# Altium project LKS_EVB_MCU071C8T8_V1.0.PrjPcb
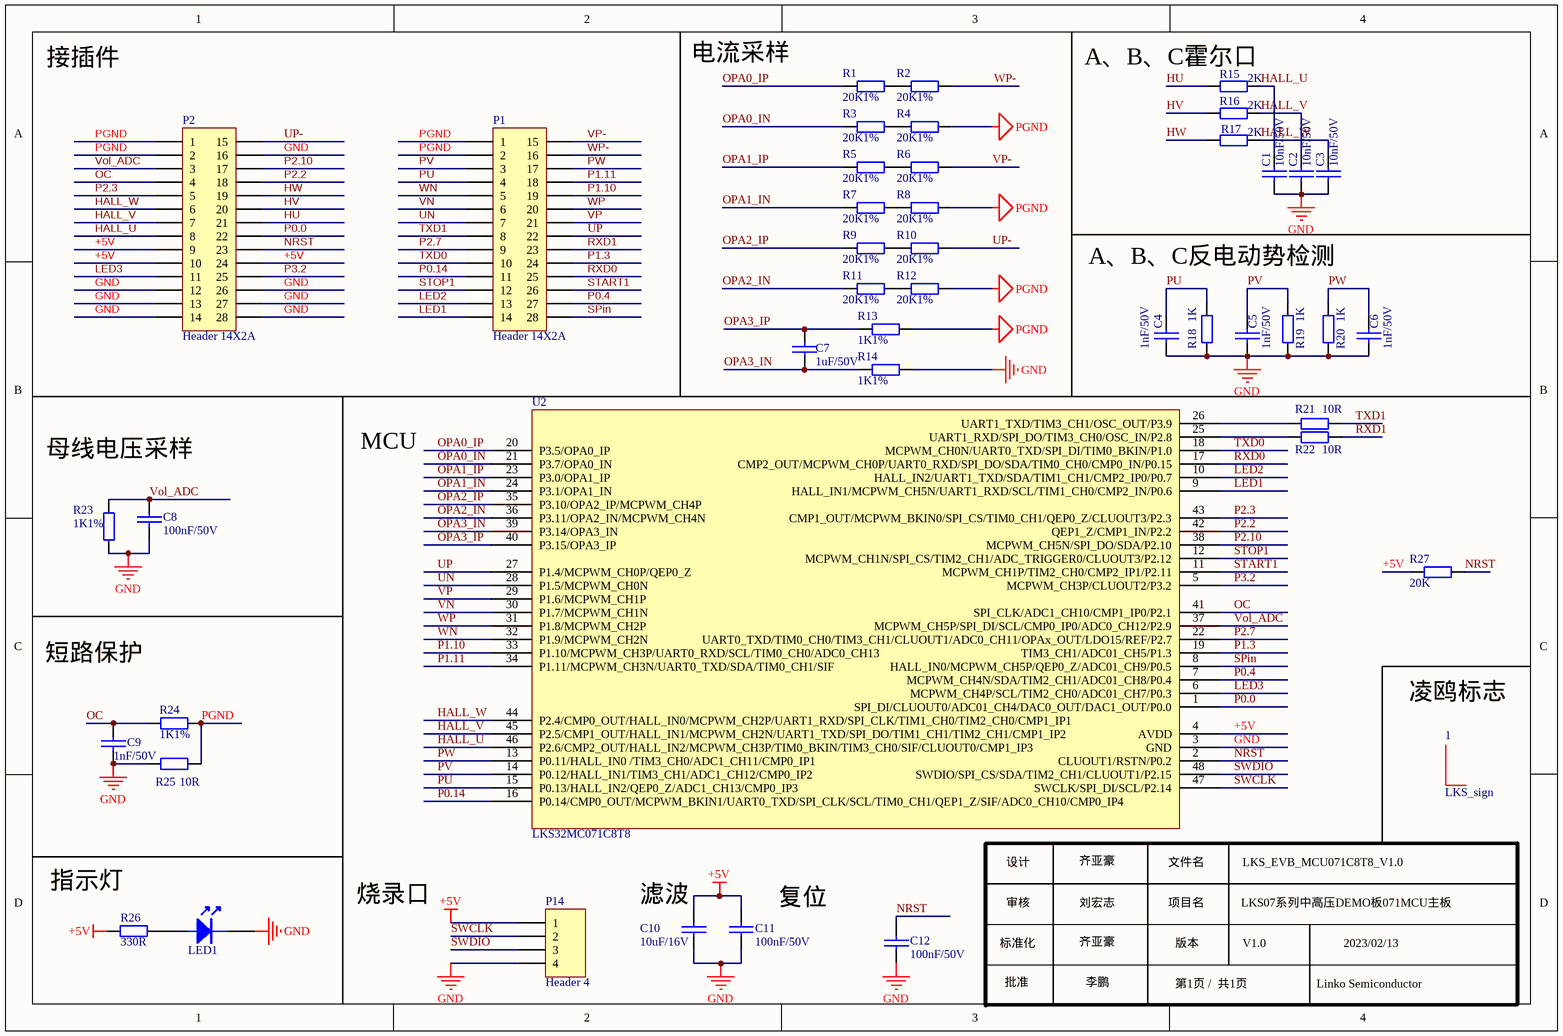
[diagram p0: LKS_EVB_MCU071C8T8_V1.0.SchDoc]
1 sheet, 45 parts. Net scope: global (net labels, ports and power ports of the same name join across sheets).
Board file: LKS_EVB_MCU071C8T8_V1.0.PcbDoc

## Sheet LKS_EVB_MCU071C8T8_V1.0.SchDoc
size A4; SheetNumber: 1; SheetTotal: 1

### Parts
1  LKS_sign  [LKS_LOGO2]
C1  10nF/50V  [0603C]
C2  10nF/50V  [0603C]
C3  10nF/50V  [0603C]
C4  1nF/50V  [0603C]
C5  1nF/50V  [0603C]
C6  1nF/50V  [0603C]
C7  1uF/50V  [0603C]
C8  100nF/50V  [0603C]
C9  1nF/50V  [0603C]
C10  10uF/16V  [0603C]
C11  100nF/50V  [0603C]
C12  100nF/50V  [0603C]
LED1  LED  [LED 0603R]  (value not drawn)
P1  Header 14X2A  [HDR2X14_CEN]
P2  Header 14X2A  [HDR2X14_CEN]
P14  Header 4  [HDR1X4]
R1  20K1%  [0603R]
R2  20K1%  [0603R]
R3  20K1%  [0603R]
R4  20K1%  [0603R]
R5  20K1%  [0603R]
R6  20K1%  [0603R]
R7  20K1%  [0603R]
R8  20K1%  [0603R]
R9  20K1%  [0603R]
R10  20K1%  [0603R]
R11  20K1%  [0603R]
R12  20K1%  [0603R]
R13  1K1%  [0603R]
R14  1K1%  [0603R]
R15  2K  [0603R]
R16  2K  [0603R]
R17  2K  [0603R]
R18  1K  [0603R]
R19  1K  [0603R]
R20  1K  [0603R]
R21  10R  [0603R]
R22  10R  [0603R]
R23  1K1%  [0603R]
R24  1K1%  [0603R]
R25  10R  [0603R]
R26  330R  [0603R]
R27  20K  [0603R]
U2  LKS32MC071C8T8  [TQFP48]

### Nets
+5V: C10.2 C11.2 P2.9 P2.10 P2.24 P14.1 R26.1 R27.2 U2.4(AVDD)
GND: C1.2 C2.2 C3.2 C4.2 C5.2 C6.2 C8.1 C9.1 C10.1 C11.1 C12.2 LED1.2(K) P2.12 P2.13 P2.14 P2.16 P2.26 P2.27 P2.28 P14.4 R14.1 R18.2 R19.2 R20.2 R23.1 R25.2 U2.3(GND)
PGND: P1.1 P1.2 P2.1 P2.2 R4.1 R8.1 R12.1 R13.1 R24.2 R25.1
HALL_U: C1.1 P2.8 R15.2 U2.46(P2.6/CMP2_OUT/HALL_IN2/MCPWM_CH3P/TIM0_BKIN/TIM3_CH0/SIF/CLUOUT0/CMP1_IP3)
HALL_V: C2.1 P2.7 R16.2 U2.45(P2.5/CMP1_OUT/HALL_IN1/MCPWM_CH2N/UART1_TXD/SPI_DO/TIM1_CH1/TIM2_CH1/CMP1_IP2)
HALL_W: C3.1 P2.6 R17.2 U2.44(P2.4/CMP0_OUT/HALL_IN0/MCPWM_CH2P/UART1_RXD/SPI_CLK/TIM1_CH0/TIM2_CH0/CMP1_IP1)
HU: P2.21 R15.1
HV: P2.20 R16.1
HW: P2.19 R17.1
LED1: P1.14 U2.9(HALL_IN1/MCPWM_CH5N/UART1_RXD/SCL/TIM1_CH0/CMP2_IN/P0.6)
LED2: P1.13 U2.10(HALL_IN2/UART1_TXD/SDA/TIM1_CH1/CMP2_IP0/P0.7)
LED3: P2.11 U2.6(MCPWM_CH4P/SCL/TIM2_CH0/ADC01_CH7/P0.3)
NRST: C12.1 P2.23 R27.1 U2.2(CLUOUT1/RSTN/P0.2)
OC: C9.2 P2.4 R24.1 U2.41(SPI_CLK/ADC1_CH10/CMP1_IP0/P2.1)
OPA0_IN: R3.2 U2.21(P3.7/OPA0_IN)
OPA0_IP: R1.2 U2.20(P3.5/OPA0_IP)
OPA1_IN: R7.2 U2.24(P3.1/OPA1_IN)
OPA1_IP: R5.2 U2.23(P3.0/OPA1_IP)
OPA2_IN: R11.2 U2.36(P3.11/OPA2_IN/MCPWM_CH4N)
OPA2_IP: R9.2 U2.35(P3.10/OPA2_IP/MCPWM_CH4P)
OPA3_IN: C7.2 R14.2 U2.39(P3.14/OPA3_IN)
OPA3_IP: C7.1 R13.2 U2.40(P3.15/OPA3_IP)
P0.0: P2.22 U2.1(SPI_DI/CLUOUT0/ADC01_CH4/DAC0_OUT/DAC1_OUT/P0.0)
P0.4: P1.27 U2.7(MCPWM_CH4N/SDA/TIM2_CH1/ADC01_CH8/P0.4)
P0.14: P1.11 U2.16(P0.14/CMP0_OUT/MCPWM_BKIN1/UART0_TXD/SPI_CLK/SCL/TIM0_CH1/QEP1_Z/SIF/ADC0_CH10/CMP0_IP4)
P1.3: P1.24 U2.19(TIM3_CH1/ADC01_CH5/P1.3)
P1.10: P1.19 U2.33(P1.10/MCPWM_CH3P/UART0_RXD/SCL/TIM0_CH0/ADC0_CH13)
P1.11: P1.18 U2.34(P1.11/MCPWM_CH3N/UART0_TXD/SDA/TIM0_CH1/SIF)
P2.2: P2.18 U2.42(QEP1_Z/CMP1_IN/P2.2)
P2.3: P2.5 U2.43(CMP1_OUT/MCPWM_BKIN0/SPI_CS/TIM0_CH1/QEP0_Z/CLUOUT3/P2.3)
P2.7: P1.9 U2.22(UART0_TXD/TIM0_CH0/TIM3_CH1/CLUOUT1/ADC0_CH11/OPAx_OUT/LDO15/REF/P2.7)
P2.10: P2.17 U2.38(MCPWM_CH5N/SPI_DO/SDA/P2.10)
P3.2: P2.25 U2.5(MCPWM_CH3P/CLUOUT2/P3.2)
PU: C4.1 P1.4 R18.1 U2.15(P0.13/HALL_IN2/QEP0_Z/ADC1_CH13/CMP0_IP3)
PV: C5.1 P1.3 R19.1 U2.14(P0.12/HALL_IN1/TIM3_CH1/ADC1_CH12/CMP0_IP2)
PW: C6.1 P1.17 R20.1 U2.13(P0.11/HALL_IN0_/TIM3_CH0/ADC1_CH11/CMP0_IP1)
RXD0: P1.25 U2.17(CMP2_OUT/MCPWM_CH0P/UART0_RXD/SPI_DO/SDA/TIM0_CH0/CMP0_IN/P0.15)
RXD1: P1.23 R22.2
SPin: P1.28 U2.8(HALL_IN0/MCPWM_CH5P/QEP0_Z/ADC01_CH9/P0.5)
START1: P1.26 U2.11(MCPWM_CH1P/TIM2_CH0/CMP2_IP1/P2.11)
STOP1: P1.12 U2.12(MCPWM_CH1N/SPI_CS/TIM2_CH1/ADC_TRIGGER0/CLUOUT3/P2.12)
SWCLK: P14.2 U2.47(SWCLK/SPI_DI/SCL/P2.14)
SWDIO: P14.3 U2.48(SWDIO/SPI_CS/SDA/TIM2_CH1/CLUOUT1/P2.15)
TXD0: P1.10 U2.18(MCPWM_CH0N/UART0_TXD/SPI_DI/TIM0_BKIN/P1.0)
TXD1: P1.8 R21.1
UN: P1.7 U2.28(P1.5/MCPWM_CH0N)
UP: P1.22 U2.27(P1.4/MCPWM_CH0P/QEP0_Z)
UP-: P2.15 R10.1
VN: P1.6 U2.30(P1.7/MCPWM_CH1N)
Vol_ADC: C8.2 P2.3 R23.2 U2.37(MCPWM_CH5P/SPI_DI/SCL/CMP0_IP0/ADC0_CH12/P2.9)
VP: P1.21 U2.29(P1.6/MCPWM_CH1P)
VP-: P1.15 R6.1
WN: P1.5 U2.32(P1.9/MCPWM_CH2N)
WP: P1.20 U2.31(P1.8/MCPWM_CH2P)
WP-: P1.16 R2.1
NetLED1_1: LED1.1(A) R26.2
NetR1_1: R1.1 R2.2
NetR3_1: R3.1 R4.2
NetR5_1: R5.1 R6.2
NetR7_1: R7.1 R8.2
NetR9_1: R9.1 R10.2
NetR11_1: R11.1 R12.2
NetR21_2: R21.2 U2.26(UART1_TXD/TIM3_CH1/OSC_OUT/P3.9)
NetR22_1: R22.1 U2.25(UART1_RXD/SPI_DO/TIM3_CH0/OSC_IN/P2.8)

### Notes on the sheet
- 接插件
- 电流采样
- A、B、C霍尔口
- A、B、C反电动势检测
- MCU
- 母线电压采样
- 短路保护
- (near 1) 凌鸥标志
- (near R26) 指示灯
- 烧录口
- (near C10) 滤波
- (near C11) 复位
- 设计
- 审核
- 齐亚豪
- 刘宏志
- 文件名
- 项目名
- LKS07系列中高压DEMO板071MCU主板
- LKS_EVB_MCU071C8T8_V1.0
- 标准化
- 批准
- 李鹏
- 版本
- 第1页 /  共1页
- V1.0
- Linko Semiconductor
- 2023/02/13

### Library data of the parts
C1-C6 = CAP: Capacitor
C7-C12 = C: Capacitor
LED1 = LED: LED_Light
P1 P2 = Header 14X2A: Header, 14-Pin, Dual row
P14 = Header 4: Header, 4-Pin
R1-R25 R27 = Res: Resistor; Value: K
R26 = Res: Resistor; Value: 330
U2 = LKS32MC071CBT8: 芯片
